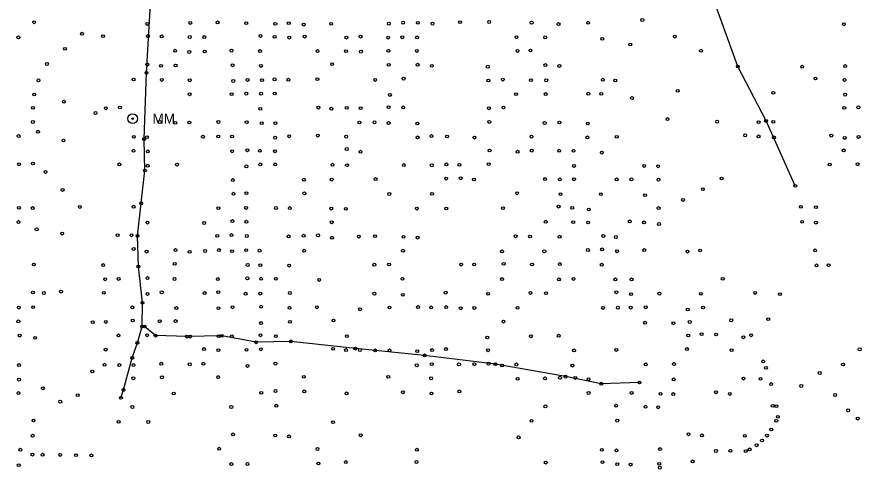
# Model space of a CAD drawing. Extents: x 20503438 to 20508873, y 7964251 to 7984667.
# Drawn here: x 20506686 to 20507270, y 7970563 to 7970876 of the extents above; entities that cross this region are included whole.
import ezdxf

# ---------------------------------------------------------------- set-up
doc = ezdxf.new("R2010")
doc.units = 0
for name, color, linetype in [('SurDrainageArrowDown', 7, 'Continuous'), ('SurRoadPoints', 7, 'Continuous'), ('SurSurveyPoints', 7, 'Continuous')]:
    doc.layers.add(name, color=color, linetype=linetype)

msp = doc.modelspace()

# ---------------------------------------------------------------- linework, layer by layer
at = {"layer": 'SurDrainageArrowDown'}
for points in [[(20507224.7, 7970759.18), (20507204.45, 7970804.1), (20507184.9, 7970841.74), (20507169.23, 7970884.93), (20507146.3, 7970924.33), (20507137.63, 7970936.09), (20507135.68, 7970938.54), (20507132.89, 7970943.61), (20507112.81, 7970984), (20507088.76, 7971026.9), (20507065.73, 7971065.56), (20507040.06, 7971109.35), (20507016.49, 7971152.89), (20506989.99, 7971198.73)], [(20506758.23, 7970612.66), (20506759.96, 7970618.07), (20506766.03, 7970640.28), (20506769.58, 7970650.69), (20506772.91, 7970661.98), (20506773.11, 7970678.32), (20506770.25, 7970703.37), (20506769.67, 7970724.66), (20506772.21, 7970747.11), (20506774.83, 7970769.77), (20506774.2, 7970791.54), (20506775.89, 7970837.25), (20506778.93, 7970889.1), (20506783.31, 7970939.45), (20506783.6, 7970964.79), (20506784.75, 7971014.54), (20506785.47, 7971061.82), (20506786.12, 7971108.98), (20506786.8, 7971156.01), (20506790.11, 7971182.82)], [(20507116.88, 7970623.21), (20507090.46, 7970622.38), (20507065.73, 7970627.27), (20507017.24, 7970635.91), (20506968.26, 7970641.97), (20506920.38, 7970646.65), (20506875.75, 7970651.65), (20506851.74, 7970651.03), (20506827.96, 7970655.49), (20506803.89, 7970655), (20506782.2, 7970655.65), (20506774.48, 7970661.98)]]:
    msp.add_lwpolyline(points, dxfattribs=at)
at = {"layer": 'SurRoadPoints'}
for radius in [3.43, 0.571]:
    msp.add_circle((20506766.31, 7970805.65), radius, dxfattribs=at)
at = {"layer": 'SurSurveyPoints'}
for centre in [(20506698.19, 7970872.29), (20506776.41, 7970871.16), (20506806.13, 7970871.84), (20506825.04, 7970872.17), (20506844.91, 7970871.64), (20506864.99, 7970871.2), (20506874.24, 7970871.68), (20506884.63, 7970870.66), (20506903.65, 7970871.22), (20506943.54, 7970871.32), (20506953.44, 7970872.01), (20506963.59, 7970871.89), (20506973.71, 7970871.33), (20506992.77, 7970872.36), (20507012.89, 7970872.48), (20507042.31, 7970872), (20507060.95, 7970871.02), (20507081.42, 7970871.94), (20507118.86, 7970873.87), (20507258.3, 7970870.93), (20506687.22, 7970861.84), (20506731.29, 7970864.38), (20506745.83, 7970862.7), (20506776.89, 7970862.76), (20506786.39, 7970862.51), (20506805.78, 7970862.1), (20506815.82, 7970862.05), (20506854.75, 7970862.86), (20506864.51, 7970862.19), (20506874.63, 7970861.71), (20506885.32, 7970862.39), (20506914.13, 7970861.72), (20506924, 7970862.36), (20506943.03, 7970861.7), (20506952.83, 7970861.91), (20506963.05, 7970861.82), (20507031.79, 7970862), (20507051.63, 7970861.87), (20507091.16, 7970860.81), (20507141.38, 7970862.41), (20506719.46, 7970853.94), (20507110.53, 7970856.92), (20506795.72, 7970852.6), (20506805.47, 7970851.74), (20506816.18, 7970852.07), (20506834.68, 7970852.67), (20506854.41, 7970852.38), (20506894.17, 7970852.35), (20506913.91, 7970852.32), (20506924.19, 7970851.98), (20506943.17, 7970852.54), (20506962.89, 7970852.49), (20507032.49, 7970852.45), (20507041.53, 7970852.8), (20507159.47, 7970852.54), (20506707, 7970843.44), (20506776.4, 7970843), (20506785.96, 7970842.17), (20506796, 7970842.41), (20506835.44, 7970842.59), (20506855.03, 7970842.13), (20506904.34, 7970843.29), (20506943.47, 7970842.85), (20506963.4, 7970842.94), (20506973.22, 7970842.18), (20507011.91, 7970841.59), (20507051.81, 7970842.67), (20507061.46, 7970842.12), (20507184.9, 7970841.74), (20507229.41, 7970841.56), (20507259.16, 7970841.98), (20506775.89, 7970837.25), (20506701.13, 7970832.14), (20506766.94, 7970832.73), (20506786.49, 7970832.44), (20506805.76, 7970832.19), (20506835.87, 7970831.69), (20506845.78, 7970832.42), (20506855.81, 7970832.26), (20506864.5, 7970832.83), (20506874.03, 7970832.55), (20506894.09, 7970832.98), (20506934.05, 7970832.44), (20506953.71, 7970833.31), (20507012.37, 7970832.03), (20507022.34, 7970832.63), (20507041.84, 7970832.24), (20507052.39, 7970832.15), (20507091.55, 7970832.53), (20507100.15, 7970832.01), (20507238.64, 7970833.41), (20507258.73, 7970832.43), (20507143.37, 7970824.92), (20506698.15, 7970822.34), (20506805.69, 7970822.52), (20506834.74, 7970822.57), (20506844.86, 7970822.93), (20506855.12, 7970822.92), (20506864.57, 7970823.04), (20506944.28, 7970822.03), (20507031.55, 7970822.61), (20507052.05, 7970822.64), (20507081.51, 7970822.88), (20507090.49, 7970822.83), (20507111.73, 7970819.87), (20507209.48, 7970823.51), (20507259.22, 7970822.25), (20506697.31, 7970813.15), (20506718.67, 7970817.35), (20506747.74, 7970812.82), (20506757.52, 7970813.4), (20506854.55, 7970812.43), (20506894.76, 7970813.29), (20506903.74, 7970812.49), (20506914.38, 7970813.12), (20506923.96, 7970812.89), (20506943.32, 7970813.62), (20506953.4, 7970813.41), (20507012.76, 7970812.82), (20507022.82, 7970813.37), (20507258.6, 7970813.13), (20507268.31, 7970813.47), (20506740.63, 7970809.56), (20506697.29, 7970803.34), (20506785.05, 7970803.35), (20506795.77, 7970802.78), (20506805.5, 7970803.01), (20506825.61, 7970803.34), (20506845.18, 7970803.25), (20506855.57, 7970802.54), (20506865.02, 7970802.52), (20506923.15, 7970803.02), (20506933.63, 7970803.12), (20506943.39, 7970802.62), (20506963.26, 7970802.27), (20507013.02, 7970803.38), (20507051.31, 7970802.66), (20507061.49, 7970803), (20507081.18, 7970802.27), (20507136.29, 7970805.35), (20507170.65, 7970803.56), (20507199.31, 7970803.24), (20507204.45, 7970804.1), (20507209.43, 7970803.46), (20506700.87, 7970796.59), (20506687.45, 7970793.63), (20506718.46, 7970790.57), (20506767.1, 7970793.05), (20506774.2, 7970791.54), (20506776.18, 7970792.85), (20506814.97, 7970793.13), (20506825.49, 7970793.33), (20506835.07, 7970793.32), (20506864.91, 7970792.51), (20506874.6, 7970793.48), (20506894.36, 7970793.95), (20506914.02, 7970793.2), (20506963.44, 7970792.68), (20506973.06, 7970793.6), (20506983.81, 7970793.31), (20507002.8, 7970792.56), (20507042.18, 7970793.21), (20507080.88, 7970792.67), (20507101.16, 7970793.09), (20507190.04, 7970794.13), (20507199.28, 7970793.38), (20507209.93, 7970792.68), (20507249.61, 7970793.91), (20507258.91, 7970792.31), (20507268.48, 7970793.03), (20506766.91, 7970783.46), (20506776.79, 7970783.01), (20506835.11, 7970783.11), (20506845.68, 7970783.82), (20506854.29, 7970783.5), (20506864.84, 7970783.11), (20506914.4, 7970784.66), (20507013.25, 7970783.65), (20507042.37, 7970783.58), (20507061.34, 7970783.5), (20507071.29, 7970783.4), (20507258.2, 7970783.73), (20506923.93, 7970782.75), (20507032.58, 7970782.77), (20507090.87, 7970782.21), (20506687.73, 7970774.14), (20506697.31, 7970774.63), (20506757.1, 7970774), (20506776.75, 7970773.1), (20506796.98, 7970773.89), (20506845.01, 7970772.68), (20506854.59, 7970774.05), (20506864.9, 7970774.02), (20506904.53, 7970773.79), (20506914.58, 7970773.53), (20506953.92, 7970773.55), (20506973.19, 7970773.38), (20506983.32, 7970774.03), (20506992.32, 7970773.69), (20507012.59, 7970774.16), (20507071.56, 7970772.96), (20507120.17, 7970772.99), (20507129.84, 7970772.73), (20507248.51, 7970773.95), (20507267.77, 7970774.09), (20506706, 7970768.79), (20506774.83, 7970769.77), (20506835.62, 7970763.21), (20506884.8, 7970763.43), (20506904.01, 7970763.53), (20506934.37, 7970763.91), (20506983.14, 7970764.2), (20506993.26, 7970764.43), (20507002.36, 7970763.58), (20507051.56, 7970763.88), (20507061.81, 7970763.67), (20507071.68, 7970763.74), (20507101.17, 7970763.64), (20507111.31, 7970763.69), (20507130.05, 7970763.48), (20507173.68, 7970764.24), (20506717.85, 7970756.37), (20506836.08, 7970753.73), (20506844.97, 7970754.11), (20506885.07, 7970753.96), (20506973.39, 7970753.67), (20507032.27, 7970754.06), (20507160.76, 7970756.88), (20507224.7, 7970759.18), (20506943.81, 7970753.57), (20507062.29, 7970753.44), (20507090.2, 7970753.46), (20507120.77, 7970752.75), (20507147.03, 7970749.43), (20506687.61, 7970743.98), (20506697.19, 7970743.84), (20506729.78, 7970744.63), (20506766.96, 7970744.77), (20506772.21, 7970747.11), (20506825.64, 7970743.75), (20506844.73, 7970743.9), (20506865.39, 7970743.87), (20506875.03, 7970743.82), (20506903.68, 7970743.49), (20506913.73, 7970743.33), (20506962.85, 7970743.49), (20506983.24, 7970743.57), (20507022.47, 7970743.74), (20507060.95, 7970744.88), (20507070.43, 7970743.96), (20507081.87, 7970742.86), (20507130.14, 7970743.85), (20507228.55, 7970744.66), (20507238.97, 7970744.46), (20506687.33, 7970734.13), (20506776.6, 7970733.77), (20506815.79, 7970733.52), (20506835.27, 7970734.82), (20506844.99, 7970734.41), (20506904, 7970733.99), (20507052.03, 7970734.37), (20507071.1, 7970734.12), (20507081.39, 7970733.84), (20507110.17, 7970734.63), (20507120.1, 7970733.94), (20507130.42, 7970732.81), (20507229.41, 7970734.3), (20507238.95, 7970733.77), (20506699.91, 7970729.13), (20506717.5, 7970726.21), (20506755.9, 7970725.12), (20506765.49, 7970725), (20506769.67, 7970724.66), (20506824.82, 7970724.65), (20506834.65, 7970725.15), (20506845.25, 7970724.52), (20506884.58, 7970724.73), (20506894.52, 7970724.98), (20507091.89, 7970724.59), (20506874.19, 7970724.23), (20506904.27, 7970723.33), (20506922.76, 7970724.1), (20506933.97, 7970724.41), (20506953.67, 7970723.93), (20506963.38, 7970723.44), (20507031.22, 7970724.35), (20507041.21, 7970724.18), (20507061.67, 7970723.99), (20507100.51, 7970723.83), (20506767, 7970715.6), (20506775.96, 7970713.72), (20506795.92, 7970714.78), (20506805.68, 7970713.54), (20506816.45, 7970714.16), (20506826, 7970714.78), (20506835.06, 7970714), (20506844.8, 7970714.74), (20506854.12, 7970714.38), (20506884.94, 7970714.31), (20506953.32, 7970714.32), (20507021.86, 7970713.86), (20507051.07, 7970713.91), (20507081.27, 7970714.84), (20507090.99, 7970715.24), (20507101.42, 7970713.99), (20507120.18, 7970714.77), (20507150.15, 7970713.74), (20507158.89, 7970714.47), (20507238.46, 7970714.54), (20506697.9, 7970704.82), (20506745.89, 7970704.41), (20506770.25, 7970703.37), (20506795.4, 7970705.25), (20506845.87, 7970704.47), (20506854.66, 7970704.33), (20506874.55, 7970704.03), (20506933.48, 7970704.64), (20506943.7, 7970704.82), (20506993.58, 7970704.78), (20507002.55, 7970704.79), (20507022.95, 7970705.29), (20507042.55, 7970704.82), (20507061.77, 7970705.1), (20507090.81, 7970704.67), (20507239.32, 7970704.2), (20507247.77, 7970704.36), (20506776.58, 7970695.46), (20506747.31, 7970694.64), (20506756.55, 7970694.85), (20506795.26, 7970694.8), (20506825.23, 7970694.74), (20506845.63, 7970695.25), (20506855.19, 7970694.96), (20506865.36, 7970694.89), (20506895.31, 7970694.16), (20506952.93, 7970694.89), (20507021.87, 7970694.75), (20507061.19, 7970694.52), (20507071.29, 7970694.84), (20507100.23, 7970694.52), (20507111.46, 7970694.53), (20507174.47, 7970694.92), (20506697.3, 7970685.43), (20506704.89, 7970685.13), (20506716.72, 7970686.1), (20506746.36, 7970685.23), (20506776.53, 7970684.45), (20506786.38, 7970685.59), (20506816.06, 7970685.04), (20506825.54, 7970685.67), (20506844.42, 7970684.62), (20506854.55, 7970684.73), (20506875.03, 7970685.1), (20506933.49, 7970684.64), (20506953.22, 7970683.87), (20506982.84, 7970685.4), (20507012.24, 7970684.54), (20507041.54, 7970685.15), (20507052.27, 7970684.98), (20507100.96, 7970685.64), (20507111.11, 7970684.34), (20507130.69, 7970684.66), (20507159.35, 7970684.57), (20507196.93, 7970685.17), (20507214.03, 7970684.3), (20506773.11, 7970678.32), (20506687.58, 7970675.01), (20506697.47, 7970675.29), (20506766.03, 7970675.16), (20506796.55, 7970674.67), (20506825.69, 7970674.61), (20506835.4, 7970675.24), (20506855.23, 7970675.6), (20506874.81, 7970674.93), (20506893.72, 7970675.25), (20506923.6, 7970673.88), (20506943.99, 7970675.08), (20506963.75, 7970675.41), (20506972.82, 7970675.14), (20506983.17, 7970675.4), (20506993.24, 7970674.57), (20507002.65, 7970674.77), (20507032.55, 7970674.83), (20507091.72, 7970674.79), (20507101.92, 7970674.96), (20507110.85, 7970674.99), (20507121.22, 7970675.28), (20507150.27, 7970673.68), (20507160.89, 7970675.09), (20506766.32, 7970666.11), (20506905.21, 7970666.08), (20507180.39, 7970666.22), (20507205.99, 7970667.01), (20506687.21, 7970665.49), (20506738.67, 7970664.94), (20506747.75, 7970665.09), (20506772.91, 7970661.98), (20506774.48, 7970661.98), (20506785.01, 7970665.56), (20506795.98, 7970665.74), (20506855.14, 7970664.31), (20506875.11, 7970665.16), (20507022.82, 7970665.37), (20507120.79, 7970664.56), (20507140.37, 7970664.22), (20507151.66, 7970665.07), (20506688.21, 7970655.65), (20506756.49, 7970655.77), (20506776.31, 7970655.87), (20506782.2, 7970655.65), (20506803.89, 7970655), (20506805.97, 7970655), (20506825.86, 7970655.26), (20506827.96, 7970655.49), (20506834.88, 7970655.3), (20506854.73, 7970655.91), (20506865.35, 7970655.29), (20506914.43, 7970655.27), (20507041.81, 7970655.18), (20507061.07, 7970655.55), (20507150.63, 7970655.72), (20507159.9, 7970656.65), (20507169.95, 7970656.43), (20507188.8, 7970654.48), (20507194.15, 7970655.9), (20506698.83, 7970654.1), (20506769.58, 7970650.69), (20506851.74, 7970651.03), (20506875.75, 7970651.65), (20507011.6, 7970654.33), (20506747.64, 7970646), (20506815.71, 7970646.38), (20506825.63, 7970645.58), (20506845.04, 7970645.82), (20506854.96, 7970646.19), (20506904.98, 7970646.53), (20506913.92, 7970645.67), (20506920.38, 7970646.65), (20506923.53, 7970645.72), (20506934.05, 7970645.41), (20506943.98, 7970645.44), (20506963.16, 7970644.92), (20506973.43, 7970645.69), (20506983.04, 7970646.36), (20507012.18, 7970645.52), (20507071.62, 7970645.43), (20507100.83, 7970645.78), (20507149.7, 7970646.33), (20507180.6, 7970645.6), (20507269.22, 7970646.18), (20506766.03, 7970640.28), (20506968.26, 7970641.97), (20507202.44, 7970637.84), (20506687.73, 7970635.28), (20506746.83, 7970635.52), (20506757.08, 7970635.26), (20506766.86, 7970635.3), (20506786.09, 7970636.19), (20506805.81, 7970635.8), (20506815.22, 7970636.18), (20506845.74, 7970634.71), (20506865.04, 7970636.27), (20506962.84, 7970635.11), (20506973.18, 7970635.93), (20506992.05, 7970635.79), (20507002.68, 7970635.82), (20507012.52, 7970636.27), (20507017.24, 7970635.91), (20507021.84, 7970635.02), (20507031.77, 7970635.76), (20507070.52, 7970634.94), (20507121.24, 7970635.75), (20507140.78, 7970635.95), (20507204.35, 7970633.37), (20507257.69, 7970635.68), (20506687.73, 7970625.21), (20506738.37, 7970630.83), (20506766.76, 7970626.14), (20506786.56, 7970626.82), (20506825.43, 7970626.99), (20506884.73, 7970627.12), (20506943.15, 7970627.15), (20506972.73, 7970626.12), (20507032.56, 7970625.8), (20507051.55, 7970626.07), (20507061.92, 7970626.51), (20507065.73, 7970627.27), (20507072.46, 7970626.38), (20507081.64, 7970625.5), (20507140.58, 7970625.41), (20507188.82, 7970625.95), (20507200.6, 7970625.78), (20507241.61, 7970629.82), (20507090.46, 7970622.38), (20507116.88, 7970623.21), (20507208, 7970622.17), (20507228.8, 7970620.83), (20506687.31, 7970615.92), (20506704.22, 7970619.26), (20506728.28, 7970614.49), (20506759.96, 7970618.07), (20506794.74, 7970615.66), (20506855.28, 7970616.12), (20506865.11, 7970617.36), (20506885.03, 7970617.09), (20506914.32, 7970615.68), (20506953.27, 7970616.46), (20506973, 7970615.63), (20506992.34, 7970617.1), (20507081.73, 7970615.99), (20507111.43, 7970616), (20507131.47, 7970615.39), (20507140.3, 7970615.25), (20507169.81, 7970616.47), (20507179.38, 7970615.33), (20507252.24, 7970614.59), (20506716.2, 7970609.97), (20506758.23, 7970612.66), (20506766.09, 7970606.3), (20506834.55, 7970606.31), (20506865.62, 7970607.15), (20507051.8, 7970606.75), (20507100.76, 7970607.2), (20507121.03, 7970606.49), (20507129.82, 7970606.12), (20507209.04, 7970607.13), (20507211.64, 7970606.85), (20507261.23, 7970604), (20506697.74, 7970596.97), (20506756.55, 7970596.04), (20507042.22, 7970596.7), (20507101.53, 7970596.86), (20507211.56, 7970596.7), (20507212.6, 7970599.52), (20507267.87, 7970598.31), (20506777.08, 7970595.94), (20506904.91, 7970595.83), (20507208.09, 7970590.71), (20506697.12, 7970586.41), (20506835.77, 7970587.34), (20506864.89, 7970586.6), (20506874.52, 7970585.96), (20506924.1, 7970586.75), (20507033.27, 7970585.32), (20507150.79, 7970587.44), (20507160.13, 7970586.67), (20507189.75, 7970586.36), (20507205.05, 7970586.5), (20507197.89, 7970579.86), (20507201.66, 7970583.11), (20506688.66, 7970576.74), (20506696.92, 7970573.39), (20506703.97, 7970573.3), (20506716.17, 7970573.14), (20506727.17, 7970572.99), (20506737.72, 7970572.85), (20506826.15, 7970577.47), (20506894.15, 7970577.27), (20506962.96, 7970576.77), (20507090.84, 7970576.67), (20507100.98, 7970576.28), (20507131.16, 7970577.22), (20507169.76, 7970575.89), (20507179.75, 7970575.97), (20507190.38, 7970575.73), (20507190.38, 7970575.73), (20507193.07, 7970576.99), (20506834.56, 7970566.82), (20506845.73, 7970566.88), (20506894.75, 7970567.25), (20506913.8, 7970568.23), (20506962.67, 7970568.27), (20507052.06, 7970567.86), (20507091.29, 7970568.16), (20507130.57, 7970566.98), (20507153.67, 7970568.71), (20506687.46, 7970566.12), (20507101.56, 7970566.77), (20507110.76, 7970566.48), (20507131.01, 7970564.36)]:
    msp.add_circle(centre, 1, dxfattribs=at)

# ---------------------------------------------------------------- texts
at = {"layer": 'SurRoadPoints'}
msp.add_text('MM', height=6.995, rotation=360, dxfattribs=at).set_placement((20506780.02, 7970802.15))

doc.saveas('drawing.dxf')
